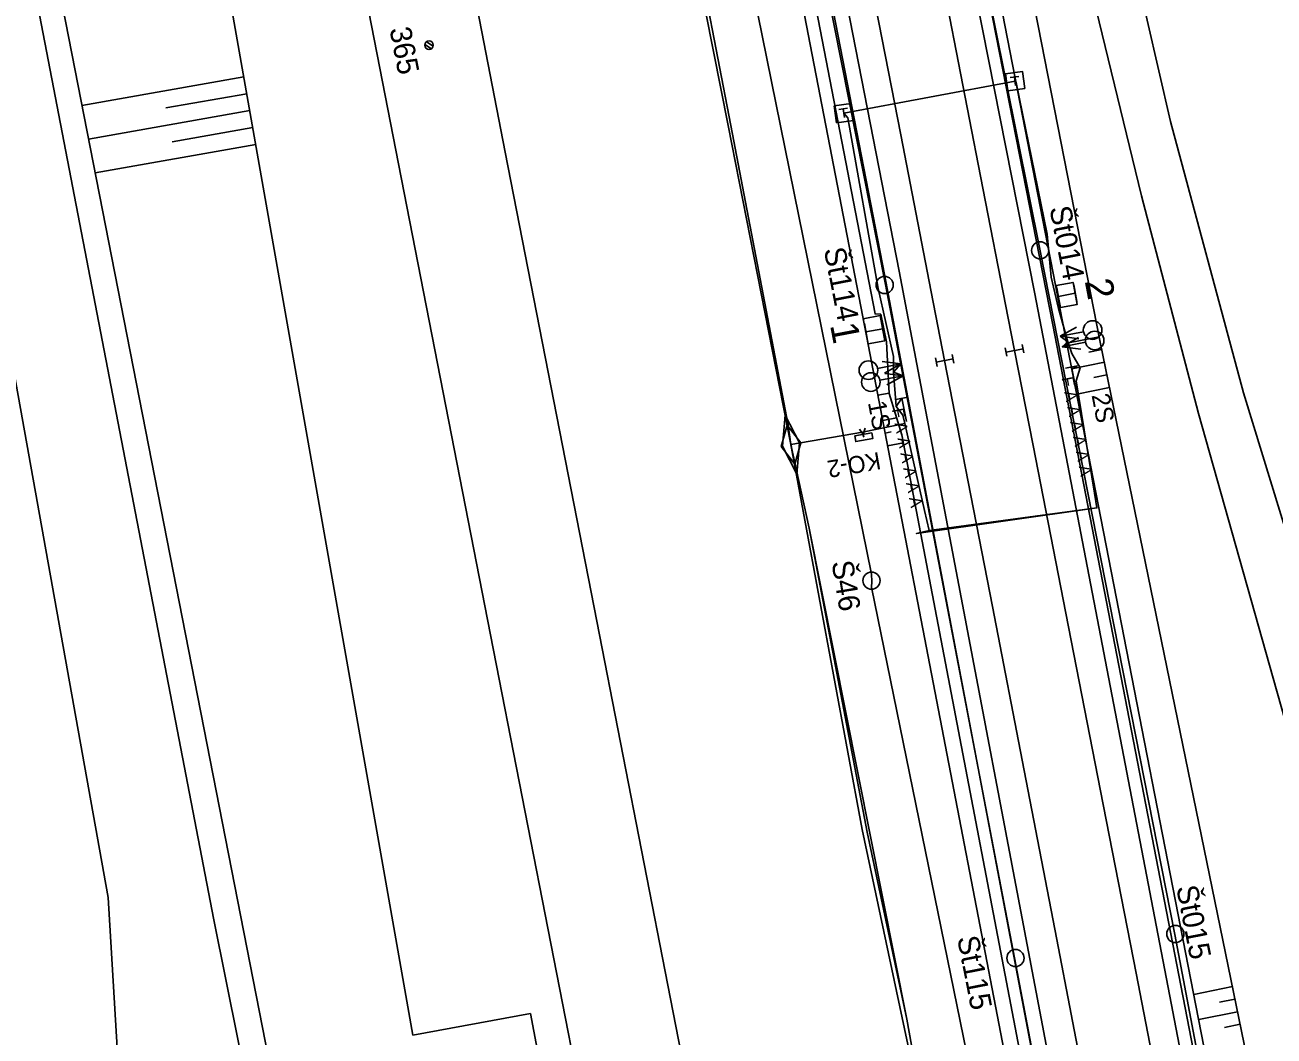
# Model space of a CAD drawing. Extents: x -545967 to -545044, y -1122650 to -1118491.
# Drawn here: x -545804.3 to -545731.6, y -1119066.4 to -1119007.5 of the extents above; entities that cross this region are included whole.
import ezdxf

# ---------------------------------------------------------------- set-up
doc = ezdxf.new("R2010")
doc.units = 0
for name, color, linetype in [('Vrstva 1', 7, 'Continuous'), ('Vrstva 1 - Koleje', 7, 'Continuous'), ('Vrstva 11', 7, 'Continuous'), ('Vrstva 11 - Trakce', 7, 'Continuous'), ('Vrstva 12 - Trakce zaklady', 7, 'Continuous'), ('Vrstva 26', 7, 'Continuous'), ('Vrstva 26 - silnoproud', 7, 'Continuous'), ('Vrstva 27', 7, 'Continuous'), ('Vrstva 28 - zabzar', 7, 'Continuous'), ('Vrstva 3 - Lisy - Pocitaci body', 7, 'Continuous'), ('Vrstva 31', 7, 'Continuous'), ('Vrstva 32', 7, 'Continuous'), ('Vrstva 33 - prvky sdelzar', 7, 'Continuous'), ('Vrstva 35', 7, 'Continuous'), ('Vrstva 4 - Teren - stezky - prechody - plochy', 7, 'Continuous'), ('Vrstva 43', 7, 'Continuous'), ('Vrstva 44', 7, 'Continuous'), ('Vrstva 48', 7, 'Continuous'), ('Vrstva 49', 7, 'Continuous'), ('Vrstva 6 - Navesti', 7, 'Continuous'), ('Vrstva 62', 7, 'Continuous')]:
    doc.layers.add(name, color=color, linetype=linetype)

msp = doc.modelspace()

# ---------------------------------------------------------------- linework, layer by layer
at = {"layer": 'Vrstva 1'}
for points in [[(-545803.343, -1118697.361), (-545802.529, -1118701.559), (-545796.372, -1118733.137), (-545788.892, -1118771.626), (-545784.123, -1118796.192), (-545777.723, -1118829.089), (-545771.163, -1118862.699), (-545764.792, -1118895.381), (-545757.603, -1118932.309), (-545753.441, -1118953.648), (-545749.904, -1118971.286), (-545746.403, -1118987.4), (-545742.64, -1119003.664), (-545739.307, -1119017.411), (-545735.997, -1119030.103), (-545730.526, -1119049.438)], [(-545838.408, -1118714.766), (-545838.264, -1118718.348), (-545837.486, -1118728.28), (-545836.887, -1118733.389), (-545834.73, -1118746.875), (-545830.836, -1118767.188), (-545826.73, -1118788.319), (-545823.138, -1118806.831), (-545818.076, -1118832.894), (-545813.108, -1118858.452), (-545808.531, -1118881.987), (-545803.057, -1118910.121), (-545797.597, -1118938.248), (-545792.143, -1118966.396), (-545787.423, -1118990.652), (-545782.57, -1119015.553), (-545777.212, -1119042.997), (-545771.689, -1119071.297)], [(-545838.408, -1118714.766), (-545838.264, -1118718.348), (-545837.486, -1118728.28), (-545836.887, -1118733.389), (-545834.73, -1118746.875), (-545830.836, -1118767.188), (-545826.73, -1118788.319), (-545823.138, -1118806.831), (-545818.076, -1118832.894), (-545813.108, -1118858.452), (-545808.531, -1118881.987), (-545803.057, -1118910.121), (-545797.597, -1118938.248), (-545792.143, -1118966.396), (-545787.423, -1118990.652), (-545782.57, -1119015.553), (-545777.212, -1119042.997), (-545771.689, -1119071.297)], [(-545833.035, -1118722.987), (-545832.612, -1118725.218), (-545828.16, -1118748.155), (-545821.787, -1118781.064), (-545814.8, -1118816.973), (-545807.184, -1118856.232), (-545801.349, -1118886.259), (-545795.986, -1118913.812), (-545789.887, -1118945.221), (-545784.095, -1118975.016), (-545776.352, -1119014.883), (-545771.025, -1119042.195)], [(-545771.025, -1119042.195), (-545765.518, -1119070.46), (-545759.655, -1119100.537), (-545754.322, -1119127.883), (-545749.142, -1119154.443), (-545741.38, -1119194.232), (-545736.638, -1119218.552), (-545732.259, -1119241.007)]]:
    msp.add_lwpolyline(points, dxfattribs=at)
at = {"layer": 'Vrstva 1 - Koleje'}
for points in [[(-545764.382, -1118957.157), (-545762.439, -1118967.113), (-545760.438, -1118977.408), (-545758.491, -1118987.385), (-545756.657, -1118996.796), (-545754.778, -1119006.435), (-545753.329, -1119013.87), (-545751.549, -1119023.001), (-545750.771, -1119027.009), (-545749.861, -1119031.697), (-545747.987, -1119041.333), (-545746.141, -1119050.889), (-545744.24, -1119060.739), (-545742.567, -1119069.426), (-545740.706, -1119079.142), (-545738.925, -1119088.418), (-545738.202, -1119092.228), (-545736.387, -1119101.709)], [(-545760.159, -1118957.414), (-545758.172, -1118967.592), (-545756.196, -1118977.709), (-545754.366, -1118987.085), (-545752.464, -1118996.853), (-545750.606, -1119006.375), (-545748.676, -1119016.269), (-545747.065, -1119024.534), (-545746.698, -1119026.42), (-545745.619, -1119031.955), (-545743.713, -1119041.723), (-545741.694, -1119052.081), (-545739.622, -1119062.694), (-545737.591, -1119073.148), (-545735.605, -1119083.347), (-545733.999, -1119091.546), (-545732.95, -1119096.936)]]:
    msp.add_lwpolyline(points, dxfattribs=at)
at = {"layer": 'Vrstva 11'}
for p, q in [((-545780.661, -1119008.856), (-545781.039, -1119008.6)), ((-545780.553, -1119008.702), (-545780.937, -1119008.443))]:
    msp.add_line(p, q, dxfattribs=at)
msp.add_circle((-545780.795, -1119008.647), 0.25, dxfattribs=at)
at = {"layer": 'Vrstva 11 - Trakce'}
for p, q in [((-545743.253, -1119022.597), (-545743.07, -1119023.58)), ((-545744.236, -1119022.78), (-545744.053, -1119023.763)), ((-545743.161, -1119023.088), (-545744.145, -1119023.272)), ((-545755.446, -1119024.854), (-545755.259, -1119025.837)), ((-545754.463, -1119024.667), (-545754.276, -1119025.65)), ((-545754.37, -1119025.159), (-545755.352, -1119025.345))]:
    msp.add_line(p, q, dxfattribs=at)
at = {"layer": 'Vrstva 12 - Trakce zaklady'}
for p, q in [((-545744.271, -1119022.646), (-545743.288, -1119022.463)), ((-545744.033, -1119023.924), (-545743.05, -1119023.741)), ((-545755.506, -1119024.574), (-545754.524, -1119024.387)), ((-545755.227, -1119026.042), (-545754.245, -1119025.855))]:
    msp.add_line(p, q, dxfattribs=at)
for points in [[(-545744.033, -1119023.924), (-545744.271, -1119022.646), (-545743.288, -1119022.463), (-545743.05, -1119023.741), (-545744.033, -1119023.924)], [(-545744.271, -1119022.646), (-545744.271, -1119022.646), (-545744.033, -1119023.924), (-545744.033, -1119023.924)], [(-545743.288, -1119022.463), (-545743.288, -1119022.463), (-545743.05, -1119023.741), (-545743.05, -1119023.741)], [(-545754.524, -1119024.387), (-545754.245, -1119025.855), (-545755.227, -1119026.042), (-545755.506, -1119024.574), (-545754.524, -1119024.387)], [(-545754.524, -1119024.387), (-545754.524, -1119024.387), (-545754.245, -1119025.855), (-545754.245, -1119025.855)]]:
    msp.add_lwpolyline(points, dxfattribs=at)
at = {"layer": 'Vrstva 26'}
msp.add_lwpolyline([(-545712.501, -1119096.161), (-545714.801, -1119089.398), (-545718.283, -1119079.346), (-545722.619, -1119065.292), (-545724.086, -1119058.686), (-545725.374, -1119053.847), (-545726.477, -1119050.776), (-545727.447, -1119048.729), (-545727.234, -1119047.022), (-545727.52, -1119045.588), (-545729.026, -1119043.068), (-545733.358, -1119028.888), (-545737.609, -1119013.08), (-545738.971, -1119007.186), (-545740.966, -1118998.367), (-545742.1, -1118993.408), (-545744.469, -1118982.238), (-545746.037, -1118973.539), (-545748.64, -1118961.097)], dxfattribs=at)
at = {"layer": 'Vrstva 26 - silnoproud'}
for points in [[(-545800.897, -1118821.514), (-545796.684, -1118843.318), (-545791.187, -1118870.631), (-545788.655, -1118883.96), (-545784.722, -1118904.395), (-545780.641, -1118924.894), (-545776.901, -1118944.085), (-545772.527, -1118967.671), (-545767.712, -1118991.461), (-545763.383, -1119013.326), (-545759.751, -1119031.811), (-545755.576, -1119054.337), (-545752.321, -1119069.685), (-545748.72, -1119088.787), (-545745.498, -1119105.777)], [(-545712.501, -1119096.161), (-545714.801, -1119089.398), (-545718.283, -1119079.346), (-545722.619, -1119065.292), (-545724.086, -1119058.686), (-545725.374, -1119053.847), (-545726.477, -1119050.776), (-545727.447, -1119048.729), (-545727.234, -1119047.022), (-545727.52, -1119045.588), (-545729.026, -1119043.068), (-545733.358, -1119028.888), (-545737.609, -1119013.08), (-545738.971, -1119007.186), (-545740.966, -1118998.367), (-545742.1, -1118993.408), (-545744.469, -1118982.238), (-545746.037, -1118973.539), (-545748.64, -1118961.097)]]:
    msp.add_lwpolyline(points, dxfattribs=at)
at = {"layer": 'Vrstva 27'}
msp.add_line((-545756.001, -1119031.404), (-545755.998, -1119031.4), dxfattribs=at)
msp.add_lwpolyline([(-545756.001, -1119031.401), (-545755.016, -1119031.231), (-545754.959, -1119031.559), (-545755.944, -1119031.729)], close=True, dxfattribs=at)
msp.add_lwpolyline([(-545755.729, -1119031.016), (-545755.508, -1119031.316), (-545755.401, -1119030.959)], dxfattribs=at)
at = {"layer": 'Vrstva 28 - zabzar'}
for p, q in [((-545743.38, -1119027.38), (-545742.88, -1119027.44)), ((-545759.395, -1119033.625), (-545760.045, -1119030.195)), ((-545760.292, -1119032.018), (-545759.937, -1119030.767)), ((-545759.937, -1119030.767), (-545759.148, -1119031.802)), ((-545759.503, -1119033.053), (-545760.292, -1119032.018)), ((-545759.148, -1119031.802), (-545759.503, -1119033.053))]:
    msp.add_line(p, q, dxfattribs=at)
for points in [[(-545759.72, -1119031.91), (-545759.89, -1119030.77), (-545763.23, -1119013.33), (-545766.25, -1118997.62), (-545768.86, -1118984.55), (-545771, -1118974.69), (-545771.8, -1118970.9), (-545773.86, -1118959.07), (-545776.3, -1118946.17), (-545780.31, -1118924.98), (-545785.87, -1118897.11), (-545790.99, -1118870.65), (-545796.29, -1118843.25), (-545799.19, -1118827.63), (-545805.85, -1118794.17), (-545808.2, -1118783.5), (-545812.82, -1118758.82), (-545816.62, -1118739.16), (-545820.43, -1118719.58), (-545822.89, -1118707.67), (-545825.23, -1118696.09)], [(-545744.04, -1119025.6), (-545743.6, -1119025.93), (-545743.92, -1119026.21)], [(-545743.6, -1119025.93), (-545743.37, -1119026.6), (-545742.88, -1119027.44), (-545743.12, -1119028.19), (-545742.05, -1119034.74), (-545741.9, -1119035.6), (-545752.41, -1119037.09), (-545751.68, -1119036.92), (-545751.95, -1119035.75), (-545753.09, -1119030.68)], [(-545755.55, -1119031.19), (-545753.09, -1119030.68), (-545753.2, -1119030.19), (-545753.59, -1119029.68), (-545753.74, -1119027.68)], [(-545753.32, -1119027.21), (-545753.74, -1119027.68), (-545753.18, -1119027.9)], [(-545753.26, -1119029.21), (-545753.59, -1119029.68), (-545753.2, -1119030.19)], [(-545746.9, -1119097.66), (-545750.31, -1119079.79), (-545751.4, -1119074.13), (-545752.97, -1119065.38), (-545755.29, -1119054.49), (-545758.65, -1119036.78), (-545759.72, -1119031.91), (-545755.55, -1119031.19), (-545755.48, -1119031.48)]]:
    msp.add_lwpolyline(points, dxfattribs=at)
at = {"layer": 'Vrstva 3 - Lisy - Pocitaci body'}
for p, q in [((-545744.04, -1119025.6), (-545743.09, -1119025.064)), ((-545744.04, -1119025.6), (-545742.685, -1119025.336)), ((-545744.04, -1119025.6), (-545742.958, -1119025.741)), ((-545747.237, -1119026.27), (-545747.141, -1119026.761)), ((-545746.207, -1119026.324), (-545747.189, -1119026.516)), ((-545746.255, -1119026.079), (-545746.159, -1119026.57)), ((-545743.92, -1119026.21), (-545742.97, -1119025.674)), ((-545743.92, -1119026.21), (-545742.565, -1119025.947)), ((-545743.92, -1119026.21), (-545742.838, -1119026.351)), ((-545753.32, -1119027.21), (-545754.402, -1119027.069)), ((-545751.309, -1119026.859), (-545751.214, -1119027.35)), ((-545750.28, -1119026.914), (-545751.262, -1119027.104)), ((-545750.328, -1119026.668), (-545750.233, -1119027.159)), ((-545753.32, -1119027.21), (-545754.675, -1119027.474)), ((-545753.32, -1119027.21), (-545754.27, -1119027.746)), ((-545753.18, -1119027.9), (-545754.262, -1119027.759)), ((-545753.18, -1119027.9), (-545754.535, -1119028.163)), ((-545753.18, -1119027.9), (-545754.13, -1119028.436))]:
    msp.add_line(p, q, dxfattribs=at)
for centre in [(-545742.153, -1119025.235), (-545742.033, -1119025.845), (-545755.207, -1119027.575), (-545755.067, -1119028.265)]:
    msp.add_circle(centre, 0.542, dxfattribs=at)
at = {"layer": 'Vrstva 31'}
msp.add_lwpolyline([(-545751.4, -1119074.13), (-545752.97, -1119065.38), (-545758.65, -1119036.78), (-545759.72, -1119031.91), (-545755.55, -1119031.19), (-545753.09, -1119030.68), (-545753.2, -1119030.19), (-545753.59, -1119029.68), (-545753.74, -1119027.68), (-545753.75, -1119026.78), (-545754.64, -1119022.82), (-545756.4, -1119012.88), (-545756.64, -1119012.6), (-545746.67, -1119010.74), (-545746.6, -1119010.81), (-545744.8, -1119019.65), (-545744.57, -1119022.15), (-545744.14, -1119023.98), (-545743.6, -1119025.93), (-545743.37, -1119026.6), (-545742.88, -1119027.44), (-545743.12, -1119028.19), (-545742.05, -1119034.74), (-545741.9, -1119035.6), (-545751.68, -1119036.92), (-545751.95, -1119035.75), (-545753.09, -1119030.68)], dxfattribs=at)
at = {"layer": 'Vrstva 32'}
for points in [[(-545746.9, -1119097.66), (-545750.31, -1119079.79), (-545751.4, -1119074.13), (-545752.97, -1119065.38), (-545755.29, -1119054.49), (-545758.65, -1119036.78), (-545759.72, -1119031.91), (-545759.89, -1119030.77), (-545763.23, -1119013.33), (-545766.25, -1118997.62), (-545768.86, -1118984.55), (-545771, -1118974.69), (-545771.8, -1118970.9), (-545773.86, -1118959.07), (-545776.3, -1118946.17), (-545780.31, -1118924.98), (-545785.87, -1118897.11), (-545790.99, -1118870.65), (-545796.29, -1118843.25), (-545799.19, -1118827.63)], [(-545759.379, -1119033.626), (-545760.21, -1119032.007), (-545760.061, -1119030.194), (-545759.23, -1119031.813), (-545759.379, -1119033.626)]]:
    msp.add_lwpolyline(points, dxfattribs=at)
at = {"layer": 'Vrstva 33 - prvky sdelzar'}
for p, q in [((-545746.953, -1119010.528), (-545746.458, -1119010.457)), ((-545746.705, -1119010.492), (-545746.635, -1119010.988)), ((-545756.923, -1119012.388), (-545756.428, -1119012.317)), ((-545756.675, -1119012.352), (-545756.605, -1119012.848))]:
    msp.add_line(p, q, dxfattribs=at)
for points in [[(-545747.235, -1119010.315), (-545746.245, -1119010.175), (-545746.105, -1119011.165), (-545747.095, -1119011.305), (-545747.235, -1119010.315)], [(-545757.205, -1119012.175), (-545756.215, -1119012.035), (-545756.075, -1119013.025), (-545757.065, -1119013.165), (-545757.205, -1119012.175)]]:
    msp.add_lwpolyline(points, dxfattribs=at)
at = {"layer": 'Vrstva 35'}
msp.add_lwpolyline([(-545752.41, -1119037.09), (-545751.68, -1119036.92), (-545741.9, -1119035.6)], dxfattribs=at)
at = {"layer": 'Vrstva 4 - Teren - stezky - prechody - plochy'}
for points in [[(-545842.991, -1118523.919), (-545841.705, -1118530.396), (-545836.849, -1118554.447), (-545831.054, -1118584.604), (-545819.351, -1118645.264), (-545811.232, -1118686.911), (-545799.532, -1118746.647), (-545788.535, -1118802.768), (-545777.847, -1118857.696), (-545765.826, -1118919.341), (-545755.98, -1118970.183), (-545745.509, -1119023.121), (-545734.813, -1119078.883), (-545723.148, -1119138.675), (-545711.327, -1119199.256), (-545707.51, -1119218.932), (-545706.355, -1119218.803)], [(-545711.324, -1119247.435), (-545711.901, -1119243.963), (-545720.224, -1119201.665), (-545721.285, -1119195.757), (-545731.546, -1119141.712), (-545737.081, -1119112.42), (-545743.441, -1119079.103), (-545754.278, -1119022.005), (-545764.127, -1118971.243), (-545774.702, -1118917.119), (-545786.098, -1118858.181), (-545797.005, -1118803.413), (-545807.661, -1118749.422), (-545819.911, -1118686.431), (-545828.531, -1118641.36), (-545850.15, -1118530.525), (-545851.156, -1118525.517)], [(-545710.225, -1119247.22), (-545719.004, -1119201.386), (-545730.622, -1119141.385), (-545736.208, -1119112.206), (-545742.564, -1119078.927), (-545753.414, -1119021.814), (-545763.359, -1118970.942), (-545773.922, -1118916.709), (-545785.328, -1118858.188), (-545796.206, -1118802.914), (-545806.845, -1118748.63), (-545819.206, -1118686.191), (-545827.818, -1118641.013), (-545849.345, -1118530.249), (-545850.409, -1118525.371)], [(-545787.709, -1118802.92), (-545777.141, -1118857.583), (-545765.122, -1118918.891), (-545755.123, -1118970.549), (-545744.471, -1119024.933), (-545734.117, -1119078.34), (-545722.331, -1119138.405), (-545711.219, -1119196.145), (-545707.543, -1119214.266), (-545707.412, -1119215.197), (-545706.355, -1119218.803)]]:
    msp.add_lwpolyline(points, dxfattribs=at)
at = {"layer": 'Vrstva 43'}
for centre in [(-545745.207, -1119020.593), (-545754.267, -1119022.608), (-545755.029, -1119039.833), (-545737.333, -1119060.412), (-545746.647, -1119061.818)]:
    msp.add_circle(centre, 0.5, dxfattribs=at)
at = {"layer": 'Vrstva 44'}
for points in [[(-545799.29, -1118815.321), (-545789.933, -1118863.748), (-545789.78, -1118864.001), (-545789.769, -1118864.308), (-545781.742, -1118904.714), (-545781.69, -1118905.058), (-545781.683, -1118905.37), (-545773.843, -1118945.459), (-545773.731, -1118945.723), (-545773.748, -1118946.113), (-545765.823, -1118986.247), (-545765.769, -1118986.707), (-545765.632, -1118987.212), (-545755.037, -1119039.456), (-545755.013, -1119039.882), (-545755.034, -1119040.218), (-545744.158, -1119093.432), (-545744.096, -1119093.785), (-545744.065, -1119094.166), (-545734.822, -1119146.139)], [(-545730.081, -1119098.833), (-545737.375, -1119060.454), (-545745.202, -1119020.613), (-545752.526, -1118984.222)], [(-545739.309, -1119100.743), (-545746.711, -1119061.802), (-545754.214, -1119022.59), (-545761.475, -1118985.918), (-545761.568, -1118985.764)]]:
    msp.add_lwpolyline(points, dxfattribs=at)
at = {"layer": 'Vrstva 48'}
for p, q in [((-545741.767, -1119025.638), (-545743.658, -1119026.008)), ((-545741.62, -1119026.373), (-545742.376, -1119026.528)), ((-545741.469, -1119027.107), (-545743.367, -1119027.497)), ((-545741.318, -1119027.842), (-545742.08, -1119027.998)), ((-545754.661, -1119029.032), (-545754.003, -1119028.905)), ((-545741.168, -1119028.577), (-545743.08, -1119028.969)), ((-545754.519, -1119029.769), (-545754.227, -1119029.712)), ((-545754.377, -1119030.505), (-545753.567, -1119030.349)), ((-545754.234, -1119031.242), (-545753.878, -1119031.173)), ((-545754.092, -1119031.978), (-545753.174, -1119031.801)), ((-545734.014, -1119063.472), (-545736.261, -1119063.933)), ((-545733.864, -1119064.207), (-545734.765, -1119064.392)), ((-545733.713, -1119064.942), (-545735.974, -1119065.405)), ((-545733.562, -1119065.676), (-545734.47, -1119065.862))]:
    msp.add_line(p, q, dxfattribs=at)
at = {"layer": 'Vrstva 49'}
for points in [[(-545839.308, -1118523.198), (-545838.102, -1118529.579), (-545837.4, -1118533.485), (-545832.706, -1118555.695), (-545825.144, -1118594.377), (-545814.251, -1118651.352), (-545808.026, -1118685.152), (-545795.162, -1118750.192), (-545783.943, -1118809.71), (-545774.848, -1118856.951), (-545763.418, -1118915.038), (-545752.928, -1118968.655), (-545741.707, -1119025.946), (-545730.219, -1119081.986), (-545719.001, -1119141.326), (-545708.857, -1119196.833), (-545704.642, -1119214.146)], [(-545785.57, -1118809.023), (-545776.461, -1118857.744), (-545776.223, -1118859.028), (-545764.986, -1118916.441), (-545764.658, -1118917.886), (-545754.446, -1118970.66), (-545754.175, -1118971.989), (-545744.319, -1119022.631), (-545744.059, -1119023.95), (-545733.435, -1119078.425), (-545721.625, -1119138.52), (-545721.391, -1119139.742), (-545710.151, -1119197.125), (-545709.969, -1119198.727), (-545706.792, -1119214.135), (-545707.412, -1119215.197), (-545706.355, -1119218.803), (-545705.856, -1119218.828), (-545705.109, -1119218.756), (-545703.505, -1119218.63), (-545703.071, -1119219.321), (-545701.68, -1119223.926)], [(-545712.345, -1119247.635), (-545712.918, -1119244.626), (-545721.552, -1119201.108), (-545732.642, -1119141.942), (-545733.194, -1119140.665), (-545738.437, -1119113.17), (-545744.258, -1119082.787), (-545744.781, -1119080.348), (-545754.155, -1119031.651), (-545755.213, -1119026.18), (-545765.268, -1118974.147), (-545765.5, -1118972.759), (-545775.821, -1118920.177), (-545776.085, -1118918.771), (-545787.25, -1118861.285), (-545787.565, -1118859.78), (-545796.822, -1118811.001)], [(-545711.324, -1119247.435), (-545711.901, -1119243.963), (-545720.224, -1119201.665), (-545721.285, -1119195.757), (-545721.943, -1119195.521), (-545732.082, -1119141.82), (-545732.265, -1119140.515), (-545737.739, -1119112.717), (-545743.315, -1119083.132), (-545744.039, -1119079.561), (-545753.263, -1119031.334), (-545754.002, -1119028.935), (-545754.148, -1119025.929), (-545754.487, -1119024.319), (-545754.825, -1119024.298), (-545764.544, -1118973.992), (-545764.787, -1118972.577), (-545775.108, -1118920.03), (-545775.396, -1118918.541), (-545786.585, -1118861.093), (-545786.924, -1118859.548), (-545796.323, -1118810.897)]]:
    msp.add_lwpolyline(points, dxfattribs=at)
at = {"layer": 'Vrstva 6 - Navesti'}
for p, q in [((-545743.037, -1119027.313), (-545743.723, -1119027.447)), ((-545743.114, -1119028.74), (-545743.38, -1119027.38)), ((-545752.916, -1119029.143), (-545753.604, -1119029.277)), ((-545752.996, -1119030.571), (-545753.26, -1119029.21))]:
    msp.add_line(p, q, dxfattribs=at)
at = {"layer": 'Vrstva 62'}
for points in [[(-545831.331, -1118868.059), (-545823.578, -1118887.986), (-545813.29, -1118951.467), (-545805.4, -1118996.869), (-545793.319, -1119059.595), (-545786.903, -1119091.551)], [(-545774.893, -1119065.04), (-545773.283, -1119073.594), (-545788.35, -1119076.781), (-545809.854, -1118967.05), (-545794.565, -1118964.478), (-545793.279, -1118970.053)], [(-545798.52, -1118971.138), (-545781.739, -1119066.307)], [(-545791.582, -1119010.486), (-545801.016, -1119012.15)], [(-545791.408, -1119011.471), (-545796.116, -1119012.301)], [(-545791.235, -1119012.456), (-545800.631, -1119014.113)], [(-545791.061, -1119013.441), (-545795.75, -1119014.268)], [(-545797.993, -1119083.258), (-545799.475, -1119058.284), (-545807.351, -1119014.429)], [(-545790.887, -1119014.426), (-545800.246, -1119016.076)], [(-545781.739, -1119066.307), (-545774.893, -1119065.04)]]:
    msp.add_lwpolyline(points, dxfattribs=at)

# ---------------------------------------------------------------- texts
at = {"layer": 'Vrstva 11'}
msp.add_text('365', height=1.25, rotation=281.01547, dxfattribs=at).set_placement((-545783.102, -1119007.699))
at = {"layer": 'Vrstva 11 - Trakce'}
for s, rotation, p in [('2', 280.54926, (-545742.616, -1119022.382)), ('1', 280.76098, (-545757.447, -1119024.944))]:
    msp.add_text(s, height=1.6, rotation=rotation, dxfattribs=at).set_placement(p)
at = {"layer": 'Vrstva 27'}
msp.add_text('KO-2', height=1, rotation=189.79621, dxfattribs=at).set_placement((-545754.591, -1119032.336))
at = {"layer": 'Vrstva 43'}
for s, rotation, p in [('Št014', 280.99979, (-545744.672, -1119018.124)), ('Št114', 280.99979, (-545757.81, -1119020.532)), ('Š46', 279.31701, (-545757.359, -1119038.756)), ('Št015', 280.99979, (-545737.289, -1119057.692)), ('Št115', 280.99979, (-545750.048, -1119060.635))]:
    msp.add_text(s, height=1.25, rotation=rotation, dxfattribs=at).set_placement(p)
at = {"layer": 'Vrstva 6 - Navesti'}
for s, height, rotation, p in [('  F A A A A A A ', 0.7, 281.07387, (-545744.067, -1119027.514)), ('2S', 1.05, 280.82077, (-545742.218, -1119029.027)), ('1S', 1.05, 280.82077, (-545755.243, -1119029.456)), ('  F A A A A A A ', 0.7, 280.96133, (-545753.947, -1119029.343))]:
    msp.add_text(s, height=height, rotation=rotation, dxfattribs=at).set_placement(p)

doc.saveas('drawing.dxf')
